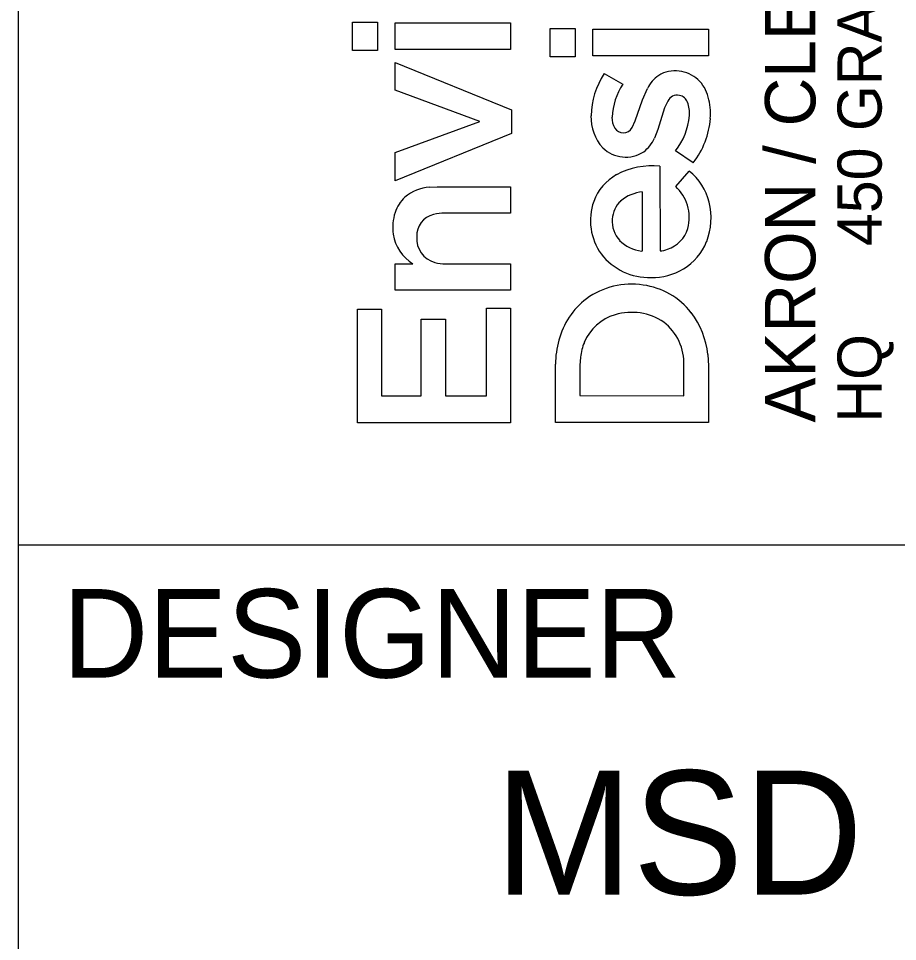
# Model space of a CAD drawing. Extents: x -4.9 to 34, y -1.2 to 22.
# Drawn here: x 32 to 32.993, y 2.552 to 3.594 of the extents above; entities that cross this region are included whole.
import ezdxf

# ---------------------------------------------------------------- set-up
doc = ezdxf.new("R2010")
doc.units = 0
doc.layers.add('SH_Border', color=7, linetype='Continuous')
doc.layers.add('SH_Data', color=7, linetype='Continuous')

msp = doc.modelspace()

# ---------------------------------------------------------------- linework, layer by layer
at = {"layer": 'SH_Border'}
for p, q in [((32, 0.5), (32, 21.5)), ((32, 3), (33.5, 3))]:
    msp.add_line(p, q, dxfattribs=at)
at = {"layer": 'SH_Data'}
for p, q in [((32.3771, 3.5582), (32.3771, 3.5903)), ((32.3771, 3.5903), (32.4054, 3.5903)), ((32.4054, 3.5903), (32.4054, 3.5582)), ((32.4254, 3.5594), (32.4254, 3.5893)), ((32.4254, 3.5893), (32.5557, 3.5893)), ((32.5557, 3.5893), (32.5557, 3.5594)), ((32.6005, 3.5511), (32.6005, 3.5832)), ((32.6005, 3.5832), (32.6289, 3.5832)), ((32.6289, 3.5832), (32.6289, 3.5511)), ((32.6489, 3.5523), (32.6489, 3.5822)), ((32.6489, 3.5822), (32.7792, 3.5822)), ((32.7792, 3.5822), (32.7792, 3.5523)), ((32.4054, 3.5582), (32.3771, 3.5582)), ((32.5557, 3.5594), (32.4254, 3.5594)), ((32.4254, 3.5133), (32.4254, 3.5446)), ((32.4254, 3.5446), (32.5567, 3.4913)), ((32.6289, 3.5511), (32.6005, 3.5511)), ((32.7792, 3.5523), (32.6489, 3.5523)), ((32.6615, 3.5321), (32.6827, 3.5203)), ((32.5212, 3.478), (32.4254, 3.5133)), ((32.7048, 3.5026), (32.7104, 3.5153)), ((32.6967, 3.4787), (32.7048, 3.5026)), ((32.7298, 3.4933), (32.7221, 3.4688)), ((32.7334, 3.501), (32.7298, 3.4933)), ((32.5567, 3.4913), (32.5567, 3.4644)), ((32.4254, 3.4429), (32.5212, 3.478)), ((32.693, 3.4712), (32.6967, 3.4787)), ((32.5567, 3.4644), (32.4254, 3.4109)), ((32.7221, 3.4688), (32.7182, 3.4592)), ((32.4254, 3.4109), (32.4254, 3.4429)), ((32.7621, 3.4314), (32.742, 3.4447)), ((32.7245, 3.4275), (32.7246, 3.3319)), ((32.7423, 3.4046), (32.7577, 3.422)), ((32.4644, 3.404), (32.4729, 3.4044)), ((32.4729, 3.4044), (32.5557, 3.4044)), ((32.5557, 3.4044), (32.5557, 3.3746)), ((32.7049, 3.3318), (32.7049, 3.3983)), ((32.5557, 3.3746), (32.4814, 3.3746)), ((32.7036, 3.3317), (32.7049, 3.3318)), ((32.4254, 3.2875), (32.4254, 3.3173)), ((32.4254, 3.3173), (32.4455, 3.3173)), ((32.4822, 3.3173), (32.5557, 3.3173)), ((32.5557, 3.3173), (32.5557, 3.2876)), ((32.5557, 3.2876), (32.4254, 3.2875)), ((32.383, 3.1379), (32.383, 3.266)), ((32.383, 3.266), (32.4101, 3.266)), ((32.4101, 3.266), (32.4101, 3.1683)), ((32.5286, 3.1683), (32.5286, 3.2672)), ((32.5286, 3.2672), (32.5557, 3.2672)), ((32.5557, 3.2672), (32.5557, 3.1379)), ((32.455, 3.1683), (32.455, 3.2549)), ((32.455, 3.2549), (32.4822, 3.2549)), ((32.4822, 3.2549), (32.4822, 3.1683)), ((32.6347, 3.2118), (32.6341, 3.2023)), ((32.7785, 3.215), (32.7792, 3.2021)), ((32.6064, 3.138), (32.6064, 3.204)), ((32.6341, 3.2023), (32.6341, 3.1684)), ((32.7515, 3.1683), (32.7515, 3.2024)), ((32.7792, 3.2021), (32.7792, 3.138)), ((32.4101, 3.1683), (32.455, 3.1683)), ((32.4822, 3.1683), (32.5286, 3.1683)), ((32.6341, 3.1684), (32.7515, 3.1683)), ((32.5557, 3.1379), (32.383, 3.1379)), ((32.7792, 3.138), (32.6064, 3.138))]:
    msp.add_line(p, q, dxfattribs=at)
for points in [[(32.3771, 3.5582), (32.3771, 3.5903), (32.4054, 3.5903), (32.4054, 3.5582)], [(32.4254, 3.5594), (32.4254, 3.5893), (32.5557, 3.5893), (32.5557, 3.5594)], [(32.6005, 3.5511), (32.6005, 3.5832), (32.6289, 3.5832), (32.6289, 3.5511)], [(32.6489, 3.5523), (32.6489, 3.5822), (32.7792, 3.5822), (32.7792, 3.5523)], [(32.4254, 3.4109), (32.4254, 3.4429), (32.5212, 3.478), (32.4254, 3.5133), (32.4254, 3.5446), (32.5567, 3.4913), (32.5567, 3.4644)], [(32.383, 3.1379), (32.383, 3.266), (32.4101, 3.266), (32.4101, 3.1683), (32.455, 3.1683), (32.455, 3.2549), (32.4822, 3.2549), (32.4822, 3.1683), (32.5286, 3.1683), (32.5286, 3.2672), (32.5557, 3.2672), (32.5557, 3.1379)]]:
    msp.add_lwpolyline(points, close=True, dxfattribs=at)
for points in [[(32.6615, 3.5321), (32.6827, 3.5203)], [(32.693, 3.4712), (32.6967, 3.4787), (32.7048, 3.5026), (32.7104, 3.5153)], [(32.7334, 3.501), (32.7298, 3.4933), (32.7221, 3.4688), (32.7182, 3.4592)], [(32.7621, 3.4314), (32.742, 3.4447)], [(32.7245, 3.4275), (32.7246, 3.3319)], [(32.7423, 3.4046), (32.7577, 3.422)], [(32.4644, 3.404), (32.4729, 3.4044), (32.5557, 3.4044), (32.5557, 3.3746), (32.4814, 3.3746)], [(32.7036, 3.3317), (32.7049, 3.3318), (32.7049, 3.3983)], [(32.4254, 3.2875), (32.4254, 3.3173), (32.4455, 3.3173)], [(32.4822, 3.3173), (32.5557, 3.3173), (32.5557, 3.2876), (32.4254, 3.2875)], [(32.7785, 3.215), (32.7792, 3.2021), (32.7792, 3.138), (32.6064, 3.138)], [(32.6347, 3.2118), (32.6341, 3.2023), (32.6341, 3.1684), (32.7515, 3.1683), (32.7515, 3.2024)], [(32.6064, 3.138), (32.6064, 3.204)]]:
    msp.add_lwpolyline(points, dxfattribs=at)
for centre, radius, start, end in [((32.7406, 3.5026), 0.0326, 80.1719, 122.5197), ((32.7406, 3.5026), 0.0326, 80.1719, 122.5197), ((32.7428, 3.4982), 0.0367, 47.7934, 84.6892), ((32.7428, 3.4982), 0.0367, 47.7934, 84.6892), ((32.7364, 3.4826), 0.0897, 146.531, 178.7571), ((32.7364, 3.4826), 0.0897, 146.531, 178.7571), ((32.7466, 3.4971), 0.0405, 125.5118, 153.4159), ((32.7466, 3.4971), 0.0405, 125.5118, 153.4159), ((32.7379, 3.4946), 0.0427, 14.9966, 46.2063), ((32.7379, 3.4946), 0.0427, 14.9966, 46.2063), ((32.7452, 3.4789), 0.0749, 146.5112, 176.9101), ((32.7452, 3.4789), 0.0749, 146.5112, 176.9101), ((32.7438, 3.4963), 0.0114, 76.6609, 155.7053), ((32.7438, 3.4963), 0.0114, 76.6609, 155.7053), ((32.744, 3.4951), 0.0126, 21.5098, 78.5262), ((32.744, 3.4951), 0.0126, 21.5098, 78.5262), ((32.7104, 3.4867), 0.0712, 355.8306, 15.3914), ((32.7104, 3.4867), 0.0712, 355.8306, 15.3914), ((32.7259, 3.4877), 0.0321, 354.5726, 22.068), ((32.7259, 3.4877), 0.0321, 354.5726, 22.068), ((32.6967, 3.4824), 0.0501, 177.5366, 222.7932), ((32.6967, 3.4824), 0.0501, 177.5366, 222.7932), ((32.6931, 3.4823), 0.0228, 178.4747, 211.0868), ((32.6931, 3.4823), 0.0228, 178.4747, 211.0868), ((32.6825, 3.4915), 0.0757, 321.811, 354.7969), ((32.6825, 3.4915), 0.0757, 321.811, 354.7969), ((32.6834, 3.4759), 0.0107, 267.716, 333.7337), ((32.6834, 3.4759), 0.0107, 267.716, 333.7337), ((32.6895, 3.4882), 0.0922, 321.9777, 355.8738), ((32.6895, 3.4882), 0.0922, 321.9777, 355.8738), ((32.6833, 3.4767), 0.0115, 212.2368, 268.3777), ((32.6833, 3.4767), 0.0115, 212.2368, 268.3777), ((32.681, 3.4758), 0.0408, 308.0877, 335.9874), ((32.681, 3.4758), 0.0408, 308.0877, 335.9874), ((32.686, 3.4753), 0.0375, 225.9854, 302.4797), ((32.686, 3.4753), 0.0375, 225.9854, 302.4797), ((32.7152, 3.3441), 0.0838, 83.615, 118.2876), ((32.7152, 3.3441), 0.0838, 83.615, 118.2876), ((32.7174, 3.3717), 0.0644, 13.5336, 51.3615), ((32.7174, 3.3717), 0.0644, 13.5336, 51.3615), ((32.7024, 3.3691), 0.0558, 118.8308, 160.6244), ((32.7024, 3.3691), 0.0558, 118.8308, 160.6244), ((32.4687, 3.3543), 0.0499, 94.9696, 130.2225), ((32.4687, 3.3543), 0.0499, 94.9696, 130.2225), ((32.7079, 3.3561), 0.0424, 94.008, 130.8817), ((32.7079, 3.3561), 0.0424, 94.008, 130.8817), ((32.7038, 3.3656), 0.0549, 19.0357, 45.4406), ((32.7038, 3.3656), 0.0549, 19.0357, 45.4406), ((32.4635, 3.3626), 0.0402, 132.2219, 161.6818), ((32.4635, 3.3626), 0.0402, 132.2219, 161.6818), ((32.7005, 3.3663), 0.0298, 132.9851, 177.179), ((32.7005, 3.3663), 0.0298, 132.9851, 177.179), ((32.7104, 3.3661), 0.0644, 160.5201, 215.7831), ((32.7104, 3.3661), 0.0644, 160.5201, 215.7831), ((32.7107, 3.3697), 0.047, 344.6059, 17.007), ((32.7107, 3.3697), 0.047, 344.6059, 17.007), ((32.7064, 3.3692), 0.0758, 339.3542, 13.3785), ((32.7064, 3.3692), 0.0758, 339.3542, 13.3785), ((32.4787, 3.3582), 0.056, 162.2736, 187.7919), ((32.4787, 3.3582), 0.056, 162.2736, 187.7919), ((32.4748, 3.3487), 0.025, 103.6865, 182.2187), ((32.4748, 3.3487), 0.025, 103.6865, 182.2187), ((32.4811, 3.3286), 0.046, 89.6049, 105.3284), ((32.4811, 3.3286), 0.046, 89.6049, 105.3284), ((32.7017, 3.365), 0.0311, 175.0013, 223.283), ((32.7017, 3.365), 0.0311, 175.0013, 223.283), ((32.7224, 3.3671), 0.035, 288.0077, 343.5508), ((32.7224, 3.3671), 0.035, 288.0077, 343.5508), ((32.4703, 3.358), 0.0476, 188.962, 238.7037), ((32.4703, 3.358), 0.0476, 188.962, 238.7037), ((32.4773, 3.3456), 0.0276, 175.5854, 255.1439), ((32.4773, 3.3456), 0.0276, 175.5854, 255.1439), ((32.7089, 3.3736), 0.0423, 225.0619, 262.7974), ((32.7089, 3.3736), 0.0423, 225.0619, 262.7974), ((32.7189, 3.3652), 0.0626, 300.9427, 338.7323), ((32.7189, 3.3652), 0.0626, 300.9427, 338.7323), ((32.7125, 3.3705), 0.0687, 217.7452, 271.6543), ((32.7125, 3.3705), 0.0687, 217.7452, 271.6543), ((32.7247, 3.3522), 0.0202, 269.7003, 294.8711), ((32.7247, 3.3522), 0.0202, 269.7003, 294.8711), ((32.4818, 3.3595), 0.0422, 254.0916, 270.5284), ((32.4818, 3.3595), 0.0422, 254.0916, 270.5284), ((32.7155, 3.3724), 0.0706, 269.2048, 300.3341), ((32.7155, 3.3724), 0.0706, 269.2048, 300.3341), ((32.6923, 3.2079), 0.0864, 81.194, 125.9984), ((32.6923, 3.2079), 0.0864, 81.194, 125.9984), ((32.6946, 3.2113), 0.0827, 37.8521, 82.402), ((32.6946, 3.2113), 0.0827, 37.8521, 82.402), ((32.6939, 3.2089), 0.0865, 127.2362, 165.148), ((32.6939, 3.2089), 0.0865, 127.2362, 165.148), ((32.6889, 3.2078), 0.054, 106.1881, 157.3861), ((32.6889, 3.2078), 0.054, 106.1881, 157.3861), ((32.6928, 3.1986), 0.0639, 55.6727, 107.2093), ((32.6928, 3.1986), 0.0639, 55.6727, 107.2093), ((32.6859, 3.2057), 0.0931, 5.7333, 37.304), ((32.6859, 3.2057), 0.0931, 5.7333, 37.304), ((32.6929, 3.205), 0.0587, 357.4662, 52.2665), ((32.6929, 3.205), 0.0587, 357.4662, 52.2665), ((32.7143, 3.2028), 0.1078, 164.7861, 179.3704), ((32.7143, 3.2028), 0.1078, 164.7861, 179.3704), ((32.6983, 3.2039), 0.0641, 157.3571, 172.9275), ((32.6983, 3.2039), 0.0641, 157.3571, 172.9275)]:
    msp.add_arc(centre, radius, start, end, dxfattribs=at)

# ---------------------------------------------------------------- texts
for s, height, p in [('450 GRANT ST., AKRON, OH  44311', 0.049846, (32.9749, 3.3374)), ('AKRON / CLEVELAND / COLUMBUS', 0.056969, (32.9001, 3.138)), ('HQ ', 0.04985, (32.9749, 3.138))]:
    msp.add_text(s, height=height, rotation=90, dxfattribs=at).set_placement(p)
for s, height, p in [('DESIGNER', 0.1, (32.05, 2.85)), ('MSD', 0.14, (32.5379, 2.605))]:
    msp.add_text(s, height=height, dxfattribs=at).set_placement(p)

doc.saveas('drawing.dxf')
